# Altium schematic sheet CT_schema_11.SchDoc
size 387 x 278 mm
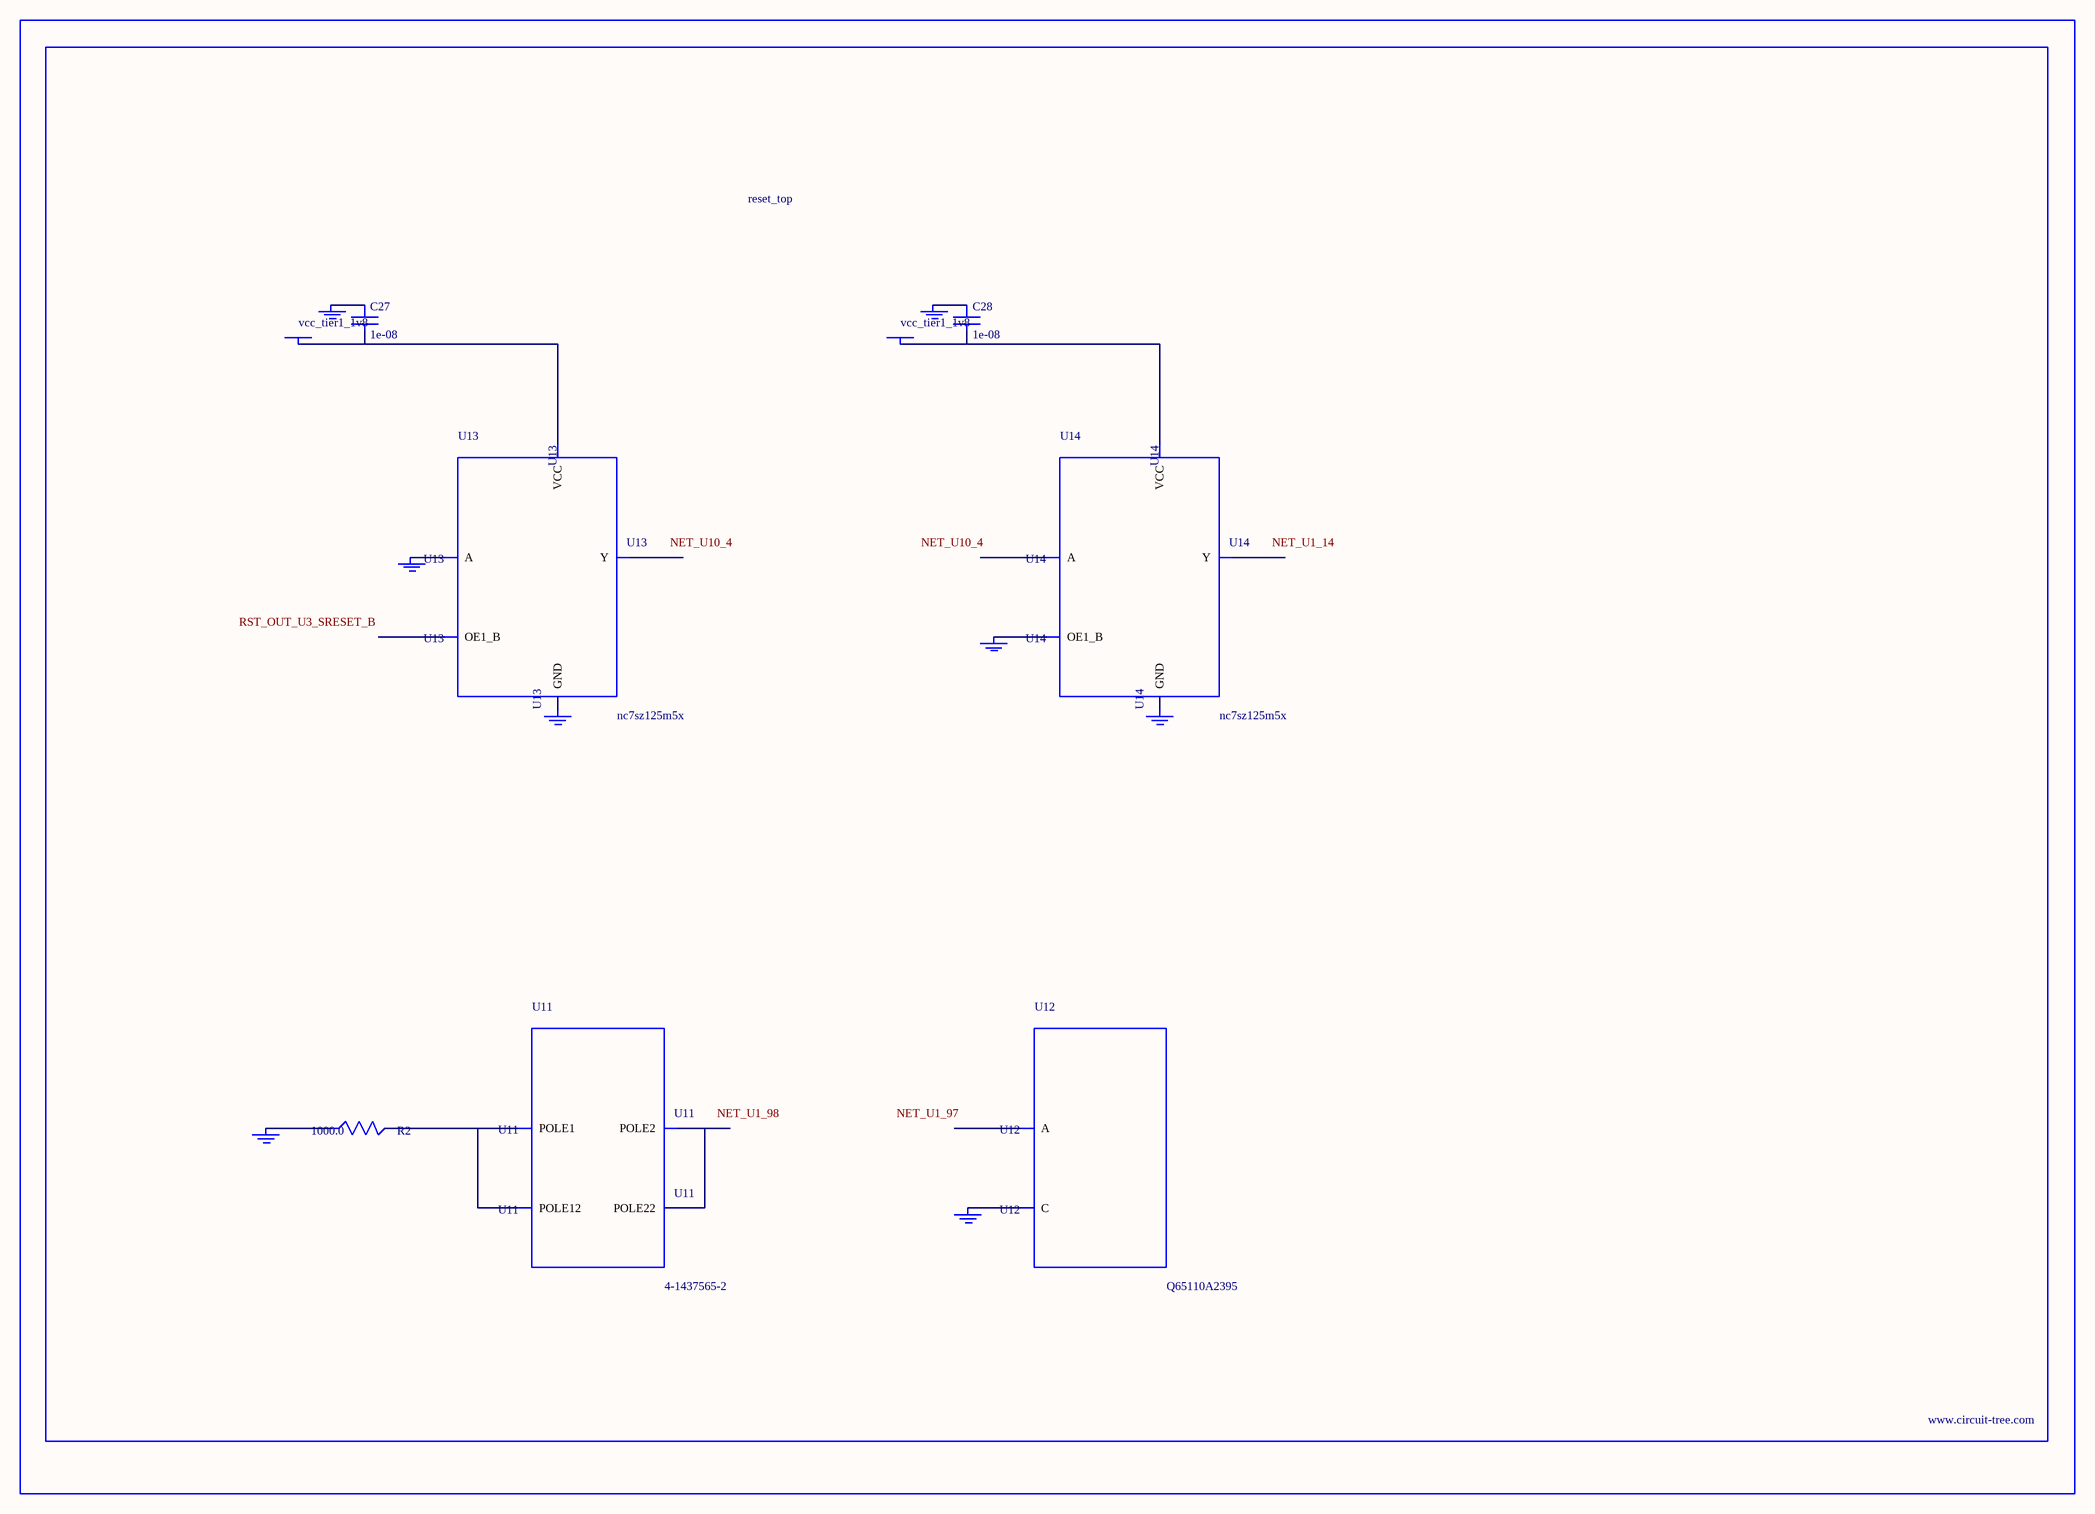
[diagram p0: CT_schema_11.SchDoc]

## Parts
BORDER10  (no value)
C27  1e-08  [C0402]
C28  1e-08  [C0402]
GND_INSTANCE_10_0  (no value)
GND_INSTANCE_10_1  (no value)
GND_INSTANCE_10_2  (no value)
GND_INSTANCE_10_3  (no value)
GND_INSTANCE_10_4  (no value)
GND_INSTANCE_10_5  (no value)
GND_INSTANCE_10_6  (no value)
GND_INSTANCE_10_7  (no value)
POWER_INSTANCE_10_0  vcc_tier1_1v8
POWER_INSTANCE_10_1  vcc_tier1_1v8
R2  1000.0  [R0603]
U11  4-1437565-2  [SW_4-1437565-2]
U12  Q65110A2395  [LGM67K-G1J2-24-Z]
U13  nc7sz125m5x  [NC7SZ125M5X]
U14  nc7sz125m5x  [NC7SZ125M5X]

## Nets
NetC27_1: C27.1 GND_INSTANCE_10_2.0(GND)
NetC27_2: C27.2 POWER_INSTANCE_10_0.0(PWR) U13.5(VCC)
NetC28_1: C28.1 GND_INSTANCE_10_5.0(GND)
NetC28_2: C28.2 POWER_INSTANCE_10_1.0(PWR) U14.5(VCC)
NetGND_INSTANCE_10_0_0: GND_INSTANCE_10_0.0(GND) R2.1
NetGND_INSTANCE_10_1_0: GND_INSTANCE_10_1.0(GND) U12.C
NetGND_INSTANCE_10_3_0: GND_INSTANCE_10_3.0(GND) U13.2(A)
NetGND_INSTANCE_10_4_0: GND_INSTANCE_10_4.0(GND) U13.3(GND)
NetGND_INSTANCE_10_6_0: GND_INSTANCE_10_6.0(GND) U14.1(OE1_B)
NetGND_INSTANCE_10_7_0: GND_INSTANCE_10_7.0(GND) U14.3(GND)
NetR2_2: R2.2 U11.1(POLE1) U11.2(POLE12)
NetU11_3: U11.3(POLE2) U11.4(POLE22)

Not connected (* = marked no-connect by the designer): U12 A; U13 1(OE1_B) 4(Y); U14 2(A) 4(Y)

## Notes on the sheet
- Labels drawn without touching a wire or pin: NET_U1_14, NET_U1_97, NET_U1_98, NET_U10_4, RST_OUT_U3_SRESET_B

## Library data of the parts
BORDER10 = BORDER_PAGE10
C27 C28 = C0402C103K3RAC
GND_INSTANCE_10_0-GND_INSTANCE_10_7 = GND
POWER_INSTANCE_10_0 POWER_INSTANCE_10_1 = PWR
R2 = RC0603JR-071KL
